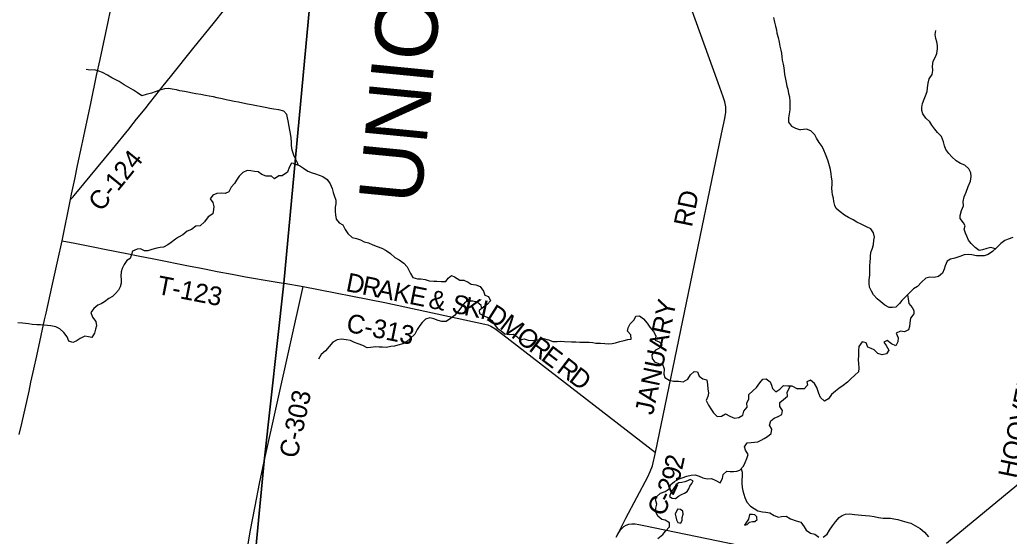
# Model space of a CAD drawing. Extents: x 0 to 34, y 0 to 22.
# Drawn here: x 2.784 to 4.289, y 18.655 to 19.44 of the extents above; entities that cross this region are included whole.
import ezdxf

# ---------------------------------------------------------------- set-up
doc = ezdxf.new("R2010")
doc.units = 0
for name, color, linetype in [('GM_X_Corporation', 7, 'Continuous'), ('GM_X_County_Road', 7, 'Continuous'), ('GM_X_County_Road_Text', 7, 'Continuous'), ('GM_X_County_Text', 7, 'Continuous'), ('GM_X_Minor_Lake', 7, 'Continuous'), ('GM_X_Minor_River', 7, 'Continuous'), ('GM_X_State_Route', 7, 'Continuous'), ('GM_X_Township_Road', 7, 'Continuous'), ('GM_X_Township_Road_Text', 7, 'Continuous')]:
    doc.layers.add(name, color=color, linetype=linetype)

msp = doc.modelspace()

# ---------------------------------------------------------------- linework, layer by layer
at = {"layer": 'GM_X_Corporation'}
for points in [[(2.8444, 15.5792), (2.8939, 16.1007), (2.9069, 16.2381), (2.9254, 16.4061), (2.988, 17.0603), (3.0331, 17.5172), (3.0637, 17.8164), (3.0931, 18.1263), (3.1112, 18.3014), (3.1559, 18.7686), (3.1859, 19.0395), (3.2287, 19.5029), (3.2417, 19.6403), (3.2592, 19.8236), (3.2953, 20.1573), (3.3575, 20.7908), (3.3687, 20.9), (2.1, 20.9), (2.1, 14.1)], [(8.9, 20.9), (3.3687, 20.9), (3.3575, 20.7908), (3.2953, 20.1573), (3.2592, 19.8236), (3.2417, 19.6403), (3.2287, 19.5029), (3.1859, 19.0395), (3.1559, 18.7686), (3.1112, 18.3014), (3.0931, 18.1263), (3.0637, 17.8164), (3.0331, 17.5172), (2.988, 17.0603), (2.9254, 16.4061), (2.9069, 16.2381), (2.8939, 16.1007), (2.8444, 15.5792)]]:
    msp.add_lwpolyline(points, dxfattribs=at)
msp.add_lwpolyline([(3.3687, 20.9), (2.1, 20.9), (2.1, 18.2085), (2.1311, 18.2055), (2.4093, 18.1831), (2.8083, 18.1509), (3.0252, 18.1335), (3.0931, 18.1263), (3.1112, 18.3014), (3.1559, 18.7686), (3.1859, 19.0395), (3.2287, 19.5029), (3.2417, 19.6403), (3.2592, 19.8236), (3.2953, 20.1573), (3.3575, 20.7908)], close=True, dxfattribs=at)
at = {"layer": 'GM_X_County_Road'}
msp.add_line((3.156, 18.7683), (3.2151, 19.0344), dxfattribs=at)
for points in [[(3.694, 18.6581), (3.706, 18.6823), (3.7393, 18.7451), (3.7431, 18.753), (3.7463, 18.762), (3.7509, 18.7819), (3.8516, 19.2667), (3.8563, 19.2897), (3.858, 19.2993), (3.8581, 19.3074), (3.8565, 19.315), (3.8538, 19.323), (3.8463, 19.3443), (3.7701, 19.5564)], [(2.8612, 19.1669), (2.8632, 19.1687), (2.8643, 19.1697), (2.8651, 19.1707), (2.8664, 19.1722), (2.8718, 19.1787), (2.8816, 19.1905), (2.9008, 19.2139), (2.9249, 19.2432), (2.9499, 19.2738), (2.9618, 19.2887), (2.9747, 19.3048), (2.9813, 19.3131), (2.9911, 19.3252), (3.0024, 19.3396), (3.0135, 19.3534), (3.0494, 19.3983), (3.0781, 19.4339), (3.096, 19.4561), (3.1119, 19.4757), (3.1212, 19.4875), (3.1228, 19.4894)], [(2.7833, 18.8094), (2.7871, 18.8261), (2.7981, 18.8755), (2.801, 18.889), (2.8052, 18.9086), (2.8098, 18.9292), (2.8165, 18.9599), (2.8218, 18.9838), (2.8241, 18.9939), (2.8329, 19.0333), (2.8399, 19.0655), (2.8418, 19.0743), (2.8483, 19.1041), (2.8612, 19.1669), (2.8629, 19.1748), (2.8676, 19.1976), (2.8721, 19.2186), (2.8785, 19.249), (2.883, 19.2699), (2.8926, 19.3152), (2.901, 19.3554), (2.9062, 19.3794), (2.9184, 19.4368), (2.922, 19.4541)], [(3.186, 19.0393), (3.2151, 19.0344), (3.3394, 19.0101), (3.4914, 18.9773), (3.4962, 18.976), (3.5008, 18.9739), (3.5066, 18.9706), (3.5188, 18.9615), (3.7509, 18.7819)], [(3.0743, 18.368), (3.0773, 18.382), (3.0803, 18.3953), (3.0888, 18.4353), (3.1003, 18.4886), (3.1062, 18.5158), (3.109, 18.53), (3.1147, 18.5581), (3.116, 18.5646), (3.1171, 18.5698), (3.1183, 18.5759), (3.1231, 18.6007), (3.1318, 18.6458), (3.1347, 18.6614), (3.1422, 18.7005), (3.1488, 18.7349), (3.1539, 18.7585), (3.156, 18.7683)]]:
    msp.add_lwpolyline(points, dxfattribs=at)
at = {"layer": 'GM_X_Minor_Lake'}
for points in [[(3.8056, 18.7402), (3.8038, 18.741), (3.7998, 18.7392), (3.7956, 18.7375), (3.7913, 18.7364), (3.7867, 18.7357), (3.7826, 18.7333), (3.7799, 18.7294), (3.7768, 18.7247), (3.7743, 18.7205), (3.7723, 18.7149)], [(3.7723, 18.7149), (3.7766, 18.7125), (3.7815, 18.7121), (3.7863, 18.7155), (3.7907, 18.7181), (3.7951, 18.7203), (3.7991, 18.7227), (3.8018, 18.727), (3.8033, 18.731), (3.8062, 18.7347), (3.8083, 18.7391), (3.8056, 18.7402)], [(3.7845, 18.6958), (3.7812, 18.6884), (3.7819, 18.6842), (3.7828, 18.6797), (3.7849, 18.6755), (3.7877, 18.6751)], [(3.7877, 18.6751), (3.7894, 18.6748), (3.7917, 18.679), (3.7919, 18.6833), (3.793, 18.6882), (3.7928, 18.693), (3.7891, 18.6953), (3.7845, 18.6958)], [(3.8943, 18.688), (3.8925, 18.6805), (3.8894, 18.6762), (3.8867, 18.6716), (3.8907, 18.6727), (3.8943, 18.6761), (3.8985, 18.6772), (3.9024, 18.6771), (3.9055, 18.6799), (3.9054, 18.6824)], [(3.9054, 18.6824), (3.9054, 18.6841), (3.9024, 18.687), (3.8986, 18.6878), (3.8943, 18.688)]]:
    msp.add_lwpolyline(points, dxfattribs=at)
at = {"layer": 'GM_X_Minor_River'}
for points in [[(3.9306, 19.4434), (3.9322, 19.4366), (3.9337, 19.4303), (3.9349, 19.4249), (3.9356, 19.4198), (3.9376, 19.4131), (3.9391, 19.4059), (3.9401, 19.3998), (3.9417, 19.3937), (3.9426, 19.389), (3.9431, 19.3835), (3.9438, 19.3787), (3.9451, 19.3724), (3.9461, 19.3671), (3.947, 19.3623), (3.9475, 19.357), (3.9482, 19.3523), (3.9497, 19.3449), (3.9507, 19.3393), (3.9522, 19.3344), (3.9536, 19.3279), (3.9549, 19.3231), (3.9555, 19.3156), (3.9554, 19.3032), (3.9542, 19.2972), (3.9533, 19.2909), (3.9536, 19.2843), (3.9579, 19.2783), (3.9639, 19.2754), (3.9714, 19.2729)], [(4.2683, 19.0919), (4.261, 19.0935), (4.2549, 19.0922), (4.2485, 19.0901), (4.2436, 19.0894), (4.2372, 19.0938), (4.2313, 19.0999), (4.2272, 19.1047), (4.2246, 19.1108), (4.2224, 19.1155), (4.2205, 19.1214), (4.2222, 19.1267), (4.2194, 19.1315), (4.2147, 19.1376), (4.2144, 19.1425), (4.2165, 19.1499), (4.2196, 19.1569), (4.219, 19.1637), (4.2204, 19.1709), (4.2238, 19.1777), (4.2265, 19.1866), (4.2304, 19.1946), (4.2315, 19.2016), (4.2306, 19.2071), (4.2278, 19.2136), (4.2216, 19.2187), (4.215, 19.2214), (4.2082, 19.2253), (4.2018, 19.2314), (4.1971, 19.2369), (4.1926, 19.243), (4.1908, 19.2483), (4.1891, 19.2546), (4.1859, 19.2624), (4.1799, 19.2687), (4.1762, 19.2737), (4.1713, 19.28), (4.1683, 19.2847), (4.1625, 19.2906), (4.1578, 19.2971), (4.1563, 19.3021), (4.1563, 19.3068), (4.1571, 19.3125), (4.16, 19.3193), (4.1619, 19.3242), (4.1642, 19.331), (4.1648, 19.3365), (4.166, 19.3436), (4.1673, 19.3502), (4.1721, 19.3566), (4.1727, 19.3627), (4.1722, 19.3693), (4.1737, 19.3771), (4.177, 19.3835), (4.1789, 19.3888), (4.1801, 19.3956), (4.1801, 19.4008), (4.1792, 19.4067), (4.1773, 19.4114), (4.1764, 19.4175), (4.1776, 19.4236)], [(3.2013, 19.2328), (3.1984, 19.242), (3.1974, 19.2491), (3.1973, 19.254), (3.1968, 19.2603), (3.1959, 19.2671), (3.1947, 19.2723), (3.1938, 19.2776), (3.1922, 19.2863), (3.1911, 19.2911), (3.1901, 19.2961), (3.1858, 19.3011), (3.1782, 19.3029), (3.1705, 19.3039), (3.1644, 19.3052), (3.1573, 19.3064), (3.1495, 19.3082), (3.1442, 19.3091), (3.1365, 19.3109), (3.1307, 19.3119), (3.1233, 19.3132), (3.1169, 19.3146), (3.1103, 19.3158), (3.1033, 19.3174), (3.0978, 19.3185), (3.0919, 19.3197), (3.0844, 19.3215), (3.0789, 19.3227), (3.0723, 19.3238), (3.0668, 19.3248), (3.0593, 19.3264), (3.0521, 19.3275), (3.047, 19.3283), (3.0398, 19.3299), (3.0344, 19.331), (3.0276, 19.3322), (3.0223, 19.3334), (3.016, 19.3347), (3.0109, 19.3355), (3.0043, 19.3348), (2.9973, 19.3328), (2.9901, 19.3305), (2.9842, 19.3285), (2.9764, 19.3263), (2.9697, 19.3245), (2.9631, 19.3288), (2.957, 19.333), (2.95, 19.3369), (2.9427, 19.3412), (2.9352, 19.3461), (2.9293, 19.349), (2.9241, 19.3517), (2.9173, 19.3558), (2.91, 19.3597), (2.9041, 19.3619), (2.8975, 19.3637), (2.8911, 19.3636), (2.8849, 19.3643)], [(4.1876, 19.0545), (4.1814, 19.0498), (4.1751, 19.0481), (4.1685, 19.0487), (4.1622, 19.0473), (4.1556, 19.0412), (4.1497, 19.0346), (4.1434, 19.0307), (4.1385, 19.0258), (4.132, 19.0192), (4.1258, 19.0134), (4.1223, 19.0085), (4.1165, 19.0032), (4.1115, 19.0023), (4.1064, 19.0025), (4.0998, 19.0059), (4.0936, 19.0109), (4.0882, 19.0155), (4.0829, 19.022), (4.0795, 19.0271), (4.0767, 19.0336), (4.076, 19.0395), (4.0762, 19.0448), (4.0769, 19.0518), (4.0769, 19.0586), (4.0773, 19.0656), (4.0775, 19.0723), (4.0781, 19.0772), (4.0782, 19.0821), (4.0791, 19.0876), (4.0811, 19.0926), (4.0826, 19.0982), (4.0834, 19.1047), (4.084, 19.1096), (4.0829, 19.1159), (4.0788, 19.1222), (4.0718, 19.1254), (4.0641, 19.1291), (4.0571, 19.1325), (4.0518, 19.1358), (4.0448, 19.1396), (4.0384, 19.1429), (4.0318, 19.1479), (4.0258, 19.1529), (4.0238, 19.1578), (4.0225, 19.1639), (4.0221, 19.169), (4.0203, 19.1738), (4.0197, 19.1787), (4.0194, 19.1834), (4.02, 19.1899), (4.0198, 19.195), (4.0187, 19.2009), (4.0184, 19.2058), (4.0171, 19.2125), (4.0156, 19.2178), (4.0139, 19.225), (4.0117, 19.2305), (4.0098, 19.2355), (4.0072, 19.2419), (4.0044, 19.2471), (3.9999, 19.2534), (3.996, 19.26), (3.9936, 19.265), (3.9872, 19.2709), (3.9806, 19.2736), (3.9714, 19.2729)], [(3.2002, 19.2216), (3.1976, 19.2221), (3.1939, 19.2155), (3.1914, 19.2081), (3.1831, 19.2029), (3.1782, 19.2026), (3.1717, 19.198), (3.1669, 19.2022), (3.1587, 19.202), (3.1521, 19.2049), (3.1469, 19.2086), (3.1412, 19.2094), (3.1353, 19.2105), (3.1302, 19.2107), (3.1236, 19.208), (3.1178, 19.202), (3.1138, 19.196), (3.1109, 19.1911), (3.1055, 19.1854), (3.102, 19.1783), (3.0966, 19.1761), (3.0908, 19.1762), (3.0836, 19.1759), (3.0775, 19.1733), (3.0736, 19.1677), (3.0775, 19.1621), (3.079, 19.1562), (3.0789, 19.1513), (3.0779, 19.145), (3.0708, 19.1402), (3.0652, 19.1329), (3.0585, 19.1269), (3.052, 19.1262), (3.0454, 19.1212), (3.0385, 19.1184), (3.032, 19.113), (3.0255, 19.1095), (3.0207, 19.1064), (3.0142, 19.1015), (3.0094, 19.098), (3.0026, 19.0945), (2.9977, 19.0938), (2.9927, 19.0929), (2.9849, 19.0906), (2.9787, 19.0889), (2.9737, 19.0888), (2.9675, 19.0916), (2.9626, 19.0911), (2.9557, 19.0883), (2.9542, 19.0832), (2.9518, 19.077), (2.947, 19.074), (2.9426, 19.0678), (2.94, 19.0618), (2.9383, 19.0567), (2.938, 19.0502), (2.9385, 19.0455), (2.9382, 19.0394), (2.9366, 19.0337), (2.9341, 19.0288), (2.9299, 19.0238), (2.9251, 19.0191), (2.9195, 19.0161), (2.913, 19.0111), (2.9081, 19.0083), (2.9027, 19.0059), (2.8966, 19.0009), (2.8924, 18.9949), (2.8946, 18.988), (2.9, 18.9813), (2.9008, 18.9746), (2.8994, 18.9697), (2.8978, 18.9633), (2.8937, 18.9567), (2.8888, 18.9577), (2.8828, 18.9588), (2.8757, 18.9553), (2.8696, 18.9515), (2.8649, 18.9491), (2.8587, 18.9515), (2.8563, 18.958), (2.8511, 18.9647), (2.8449, 18.9701), (2.8387, 18.9733), (2.8313, 18.9747), (2.8211, 18.9756), (2.8158, 18.976), (2.8101, 18.9763), (2.8031, 18.9768), (2.7971, 18.9775), (2.788, 18.9785), (2.7812, 18.9792)], [(3.2002, 19.2216), (3.2034, 19.2205), (3.2094, 19.2184), (3.2154, 19.2143), (3.2224, 19.2098), (3.2288, 19.2075), (3.234, 19.2057), (3.2393, 19.2037), (3.2451, 19.2016), (3.2515, 19.1971), (3.2563, 19.1904), (3.2595, 19.1836), (3.2607, 19.1775), (3.2624, 19.1727), (3.2649, 19.1658), (3.2647, 19.1601), (3.2638, 19.155), (3.2638, 19.1486), (3.2641, 19.1436), (3.2653, 19.1366), (3.2698, 19.1312), (3.2756, 19.1281), (3.2789, 19.1213), (3.2832, 19.1151), (3.2897, 19.109), (3.2961, 19.1072), (3.3022, 19.1056), (3.308, 19.1025), (3.3144, 19.1007), (3.3212, 19.0976), (3.3276, 19.0954), (3.3347, 19.0926), (3.3415, 19.0893), (3.348, 19.0847), (3.3544, 19.0785), (3.3611, 19.0748), (3.3683, 19.0698), (3.3733, 19.0644), (3.3759, 19.0593), (3.3783, 19.0543), (3.3822, 19.0482), (3.3893, 19.046), (3.3942, 19.0459), (3.4008, 19.0449), (3.4067, 19.0433), (3.4137, 19.0426), (3.4186, 19.0424), (3.4252, 19.0421), (3.432, 19.0422), (3.4356, 19.0471), (3.4406, 19.0514), (3.4455, 19.0494), (3.4534, 19.0442), (3.4596, 19.0441), (3.466, 19.0412), (3.4709, 19.0379), (3.4779, 19.0371), (3.4846, 19.0347), (3.4893, 19.0274), (3.4917, 19.0211), (3.4973, 19.0192), (3.5001, 19.0127), (3.4953, 19.0078), (3.4895, 19.0028), (3.4829, 18.9981), (3.4836, 18.9932), (3.4901, 18.9897), (3.496, 18.9871), (3.5021, 18.9829), (3.5064, 18.9769), (3.5103, 18.971), (3.5165, 18.9671), (3.5219, 18.9625), (3.5283, 18.9615), (3.5346, 18.9618), (3.54, 18.9583), (3.5454, 18.9536), (3.5515, 18.9547), (3.5575, 18.9529), (3.5641, 18.9521), (3.5711, 18.9531), (3.5761, 18.9538), (3.5808, 18.9553), (3.5882, 18.9533), (3.5949, 18.9509), (3.6014, 18.951), (3.6072, 18.9511), (3.6125, 18.9507), (3.6233, 18.9505), (3.6299, 18.9503), (3.6358, 18.95), (3.6435, 18.9499), (3.6503, 18.9496), (3.6556, 18.9492), (3.6605, 18.9485), (3.6673, 18.9481), (3.6739, 18.9476), (3.679, 18.9471), (3.6854, 18.9478), (3.6902, 18.9487), (3.6968, 18.9507)], [(3.2073, 19.2191), (3.2064, 19.2224), (3.2035, 19.2285), (3.2013, 19.2328)], [(4.2945, 19.109), (4.2875, 19.1064), (4.2824, 19.1045), (4.2763, 19.0996), (4.2699, 19.0934), (4.2638, 19.0876), (4.2571, 19.0833), (4.2511, 19.0812), (4.246, 19.0811), (4.2395, 19.0809), (4.2324, 19.0825), (4.2273, 19.0831), (4.2205, 19.0824), (4.2138, 19.0801), (4.2066, 19.0777), (4.1996, 19.0762), (4.1949, 19.073), (4.1915, 19.066), (4.1903, 19.0607), (4.1876, 19.0545)], [(3.4867, 19.0008), (3.486, 19.0056), (3.4796, 19.0107), (3.4732, 19.0123), (3.4666, 19.0122), (3.4618, 19.0105), (3.4565, 19.0038), (3.4515, 18.9972), (3.4455, 18.9906), (3.439, 18.986), (3.4328, 18.9813), (3.4263, 18.9812), (3.4207, 18.983), (3.4141, 18.9854), (3.4079, 18.9866), (3.4014, 18.9849), (3.3963, 18.9799), (3.3926, 18.975), (3.3887, 18.969), (3.3851, 18.9622), (3.3778, 18.9555), (3.373, 18.951), (3.3669, 18.9475), (3.3593, 18.9453), (3.3542, 18.9438), (3.3487, 18.943), (3.3419, 18.9419), (3.3359, 18.9422), (3.3306, 18.9421), (3.3257, 18.9427), (3.3175, 18.9417), (3.3124, 18.9414), (3.3058, 18.9445), (3.2989, 18.9472), (3.293, 18.9494), (3.287, 18.9525), (3.2804, 18.9533), (3.2735, 18.9546), (3.2668, 18.9535), (3.2604, 18.9498), (3.2546, 18.9434), (3.2492, 18.9365), (3.2427, 18.9311), (3.2383, 18.9239)], [(4.1346, 19.0219), (4.1354, 19.0158), (4.1363, 19.0087), (4.1416, 19.0026), (4.144, 18.9979), (4.144, 18.9929), (4.1388, 18.9862), (4.1379, 18.9793), (4.1374, 18.9735), (4.1361, 18.9685), (4.1297, 18.9654), (4.1236, 18.9665), (4.1174, 18.9633), (4.1203, 18.9565), (4.1199, 18.9501), (4.1165, 18.9444), (4.1101, 18.9475), (4.1033, 18.9524), (4.0982, 18.9498), (4.1019, 18.9449), (4.1059, 18.9378), (4.1024, 18.9322), (4.096, 18.9305), (4.0894, 18.9326), (4.0839, 18.9382), (4.079, 18.9401), (4.0741, 18.9424), (4.0717, 18.9489), (4.0655, 18.9502), (4.0605, 18.9434), (4.0598, 18.937), (4.0597, 18.9296), (4.0595, 18.9228), (4.0598, 18.9176), (4.0602, 18.9102), (4.0599, 18.9049), (4.0542, 18.8997), (4.0482, 18.8938), (4.043, 18.8889), (4.0364, 18.8837), (4.0299, 18.8795), (4.025, 18.8752), (4.0189, 18.8703), (4.014, 18.8635), (4.0083, 18.8601), (4.0021, 18.8655), (3.9995, 18.8716), (3.9967, 18.8807), (3.9931, 18.887), (3.9869, 18.8921), (3.9814, 18.8893), (3.9823, 18.8842), (3.9774, 18.8789), (3.9671, 18.8787)], [(3.6968, 18.9507), (3.7033, 18.9525), (3.709, 18.9541), (3.7141, 18.9545), (3.7134, 18.9611), (3.7085, 18.9667), (3.7097, 18.9716), (3.7128, 18.9778), (3.7184, 18.9836), (3.7213, 18.9891), (3.7266, 18.9896), (3.733, 18.9855), (3.7386, 18.9788), (3.7425, 18.9727), (3.748, 18.9661), (3.7514, 18.9595), (3.7505, 18.953), (3.7569, 18.9503), (3.7614, 18.9453), (3.7562, 18.9404), (3.7511, 18.9377), (3.7457, 18.9307), (3.7458, 18.9252), (3.7494, 18.9198), (3.7556, 18.9175), (3.7618, 18.9163), (3.7645, 18.9092), (3.7639, 18.9013), (3.7655, 18.8963), (3.7721, 18.8922), (3.7787, 18.8906), (3.786, 18.8903), (3.7932, 18.8897), (3.8001, 18.8936), (3.8045, 18.9001), (3.8098, 18.9052), (3.8148, 18.9046), (3.8175, 18.8979), (3.8231, 18.894), (3.8292, 18.8926), (3.8304, 18.8856), (3.8305, 18.8789), (3.8317, 18.8723), (3.8309, 18.8674), (3.828, 18.8613), (3.8319, 18.8541), (3.8361, 18.847), (3.8393, 18.8422), (3.8449, 18.8368), (3.8513, 18.8371), (3.8578, 18.841), (3.8642, 18.8371), (3.8711, 18.8342), (3.8776, 18.8351), (3.8841, 18.8386), (3.8856, 18.845), (3.8903, 18.851), (3.8901, 18.8573), (3.8931, 18.8637), (3.8931, 18.8703), (3.8991, 18.8759), (3.9048, 18.881), (3.91, 18.8878), (3.9144, 18.8936), (3.9193, 18.8939), (3.9255, 18.8893), (3.9273, 18.8845), (3.929, 18.8795), (3.9342, 18.8745), (3.9403, 18.8784), (3.9457, 18.8839), (3.9523, 18.8834), (3.9585, 18.8835), (3.9671, 18.8787)], [(3.7545, 18.6514), (3.7623, 18.6572), (3.7665, 18.6622), (3.7723, 18.669), (3.7726, 18.6749), (3.766, 18.6791), (3.7609, 18.6803), (3.7545, 18.6852), (3.7522, 18.6909), (3.7517, 18.6973), (3.7533, 18.7034), (3.7511, 18.7104), (3.7536, 18.7157), (3.7588, 18.7204), (3.7658, 18.7226), (3.7717, 18.727), (3.7746, 18.7332), (3.7802, 18.7381), (3.787, 18.7422), (3.7919, 18.7436), (3.7988, 18.7458), (3.8052, 18.7476), (3.8113, 18.7479), (3.8173, 18.7462), (3.8229, 18.7436), (3.8295, 18.7418), (3.8364, 18.7427), (3.8431, 18.7394), (3.8495, 18.7361), (3.853, 18.7423), (3.8538, 18.7485), (3.8594, 18.7534), (3.8646, 18.7533), (3.8698, 18.753), (3.8747, 18.7537), (3.8794, 18.7552), (3.8852, 18.7614), (3.8877, 18.7667), (3.8902, 18.7729), (3.8922, 18.7791), (3.8879, 18.7858), (3.8863, 18.7908), (3.8903, 18.7966), (3.8966, 18.7971), (3.9017, 18.7978), (3.9066, 18.7985), (3.9117, 18.8007), (3.9165, 18.8033), (3.9213, 18.8064), (3.927, 18.8111), (3.9278, 18.8175), (3.9245, 18.8238), (3.9265, 18.8301), (3.9316, 18.8342), (3.9375, 18.8367), (3.9434, 18.8397), (3.9444, 18.8461), (3.94, 18.8521), (3.9401, 18.8583), (3.9456, 18.8628), (3.9517, 18.8675), (3.9514, 18.8737), (3.9564, 18.8835)], [(3.8814, 18.7573), (3.883, 18.7523), (3.8831, 18.7459), (3.8826, 18.7404), (3.8822, 18.7356), (3.8831, 18.729), (3.8841, 18.7235), (3.8856, 18.7185), (3.8868, 18.7134), (3.89, 18.7067), (3.8954, 18.7002), (3.9012, 18.6969), (3.907, 18.6934), (3.9138, 18.6916), (3.9187, 18.6913), (3.9251, 18.6901), (3.9317, 18.6862), (3.9383, 18.6839), (3.943, 18.6847), (3.9496, 18.685), (3.9562, 18.6814), (3.9649, 18.6782)], [(3.9649, 18.6782), (3.9724, 18.6759), (3.9771, 18.669), (3.9805, 18.6637), (3.9869, 18.6593), (3.9935, 18.6579), (3.9995, 18.6535)], [(4.0061, 18.6533), (4.0124, 18.6578), (4.016, 18.6638), (4.0202, 18.6706), (4.025, 18.6768), (4.0305, 18.6833), (4.0352, 18.6861), (4.04, 18.6885), (4.0468, 18.6886), (4.0536, 18.6878), (4.0596, 18.6874), (4.0645, 18.6866), (4.0706, 18.686), (4.077, 18.6856), (4.0836, 18.6846), (4.0902, 18.6831), (4.0974, 18.6824), (4.1034, 18.6822), (4.1087, 18.682), (4.1136, 18.6814), (4.1199, 18.6802), (4.1265, 18.6781), (4.1336, 18.6763), (4.1397, 18.6744), (4.1465, 18.6707), (4.1536, 18.6667), (4.1604, 18.661), (4.1664, 18.6537)]]:
    msp.add_lwpolyline(points, dxfattribs=at)
at = {"layer": 'GM_X_State_Route'}
for points in [[(4.1938, 18.6441), (4.3094, 18.7397)], [(3.6914, 18.6532), (3.694, 18.6581), (3.6978, 18.6644), (3.7005, 18.6672), (3.703, 18.6694), (3.7065, 18.6715), (3.7106, 18.6729), (3.715, 18.6736), (3.72, 18.6734), (3.7258, 18.6724), (3.7335, 18.6708), (3.9891, 18.6184)]]:
    msp.add_lwpolyline(points, dxfattribs=at)
at = {"layer": 'GM_X_Township_Road'}
msp.add_lwpolyline([(2.8483, 19.1041), (2.8676, 19.1003), (2.8984, 19.0943), (2.913, 19.0914), (2.9492, 19.0842), (2.9644, 19.0811), (2.9882, 19.0765), (3.0433, 19.0654), (3.0574, 19.0627), (3.0677, 19.0607), (3.0842, 19.0575), (3.1071, 19.0531), (3.1276, 19.0494), (3.1395, 19.0473), (3.1572, 19.0442), (3.1818, 19.04), (3.186, 19.0393)], dxfattribs=at)

# ---------------------------------------------------------------- texts
at = {"layer": 'GM_X_County_Road_Text'}
for s, height, rotation, p in [('C-124', 0.02841, 50.8657, (2.9078, 19.1469)), ('RD', 0.02841, 78.4938, (3.8064, 19.1237)), ('D', 0.0284, 348.54, (3.2788, 19.0278)), ('R', 0.0284, 348.5406, (3.3033, 19.0229)), ('A', 0.0284, 348.5403, (3.3261, 19.0182)), ('K', 0.0284, 348.5419, (3.3506, 19.0133)), ('E', 0.0284, 348.5413, (3.3751, 19.0083)), ('&', 0.0284, 348.5397, (3.4045, 19.0023)), ('S', 0.0284, 348.5373, (3.4397, 18.9952)), ('K', 0.0284, 348.4693, (3.4584, 18.9914)), ('I', 0.0284, 347.649, (3.4828, 18.9864)), ('JANUARY', 0.02841, 78.286, (3.7473, 18.8379)), ('D', 0.0284, 327.6386, (3.4918, 18.9849)), ('C-313', 0.02841, 348.6359, (3.2793, 18.966)), ('M', 0.0284, 322.5276, (3.5124, 18.9719)), ('O', 0.0284, 322.6293, (3.5369, 18.9531)), ('R', 0.0284, 322.6313, (3.5568, 18.938)), ('E', 0.0284, 322.6287, (3.5753, 18.9238)), ('R', 0.0284, 322.63, (3.5991, 18.9056)), ('D', 0.0284, 322.6289, (3.6177, 18.8914)), ('HOOVER', 0.02841, 78.3664, (4.2998, 18.7416)), ('C-303', 0.02841, 78.0393, (3.2061, 18.7721)), ('2', 0.0284, 77.9395, (3.7916, 18.7546)), ('9', 0.0284, 75.8789, (3.787, 18.7366)), ('2', 0.0284, 65.5462, (3.7779, 18.7154)), ('C', 0.0284, 64.7372, (3.7628, 18.6833)), ('-', 0.0284, 64.8582, (3.7728, 18.7045))]:
    msp.add_text(s, height=height, rotation=rotation, dxfattribs=at).set_placement(p)
at = {"layer": 'GM_X_County_Text'}
msp.add_text('UNION COUNTY', height=0.094697, rotation=84.4318, dxfattribs=at).set_placement((3.3936, 19.1577))
at = {"layer": 'GM_X_Township_Road_Text'}
msp.add_text('T-123', height=0.02841, rotation=348.9654, dxfattribs=at).set_placement((2.9913, 19.0234))

doc.saveas('drawing.dxf')
